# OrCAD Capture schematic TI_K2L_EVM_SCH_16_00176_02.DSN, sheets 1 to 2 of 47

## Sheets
1 PAGE19 : K2L_SOC-DDR3-1: size C; title: K2L DDR3; rev: 2.0; company: eInfochips; note: K2L EVM
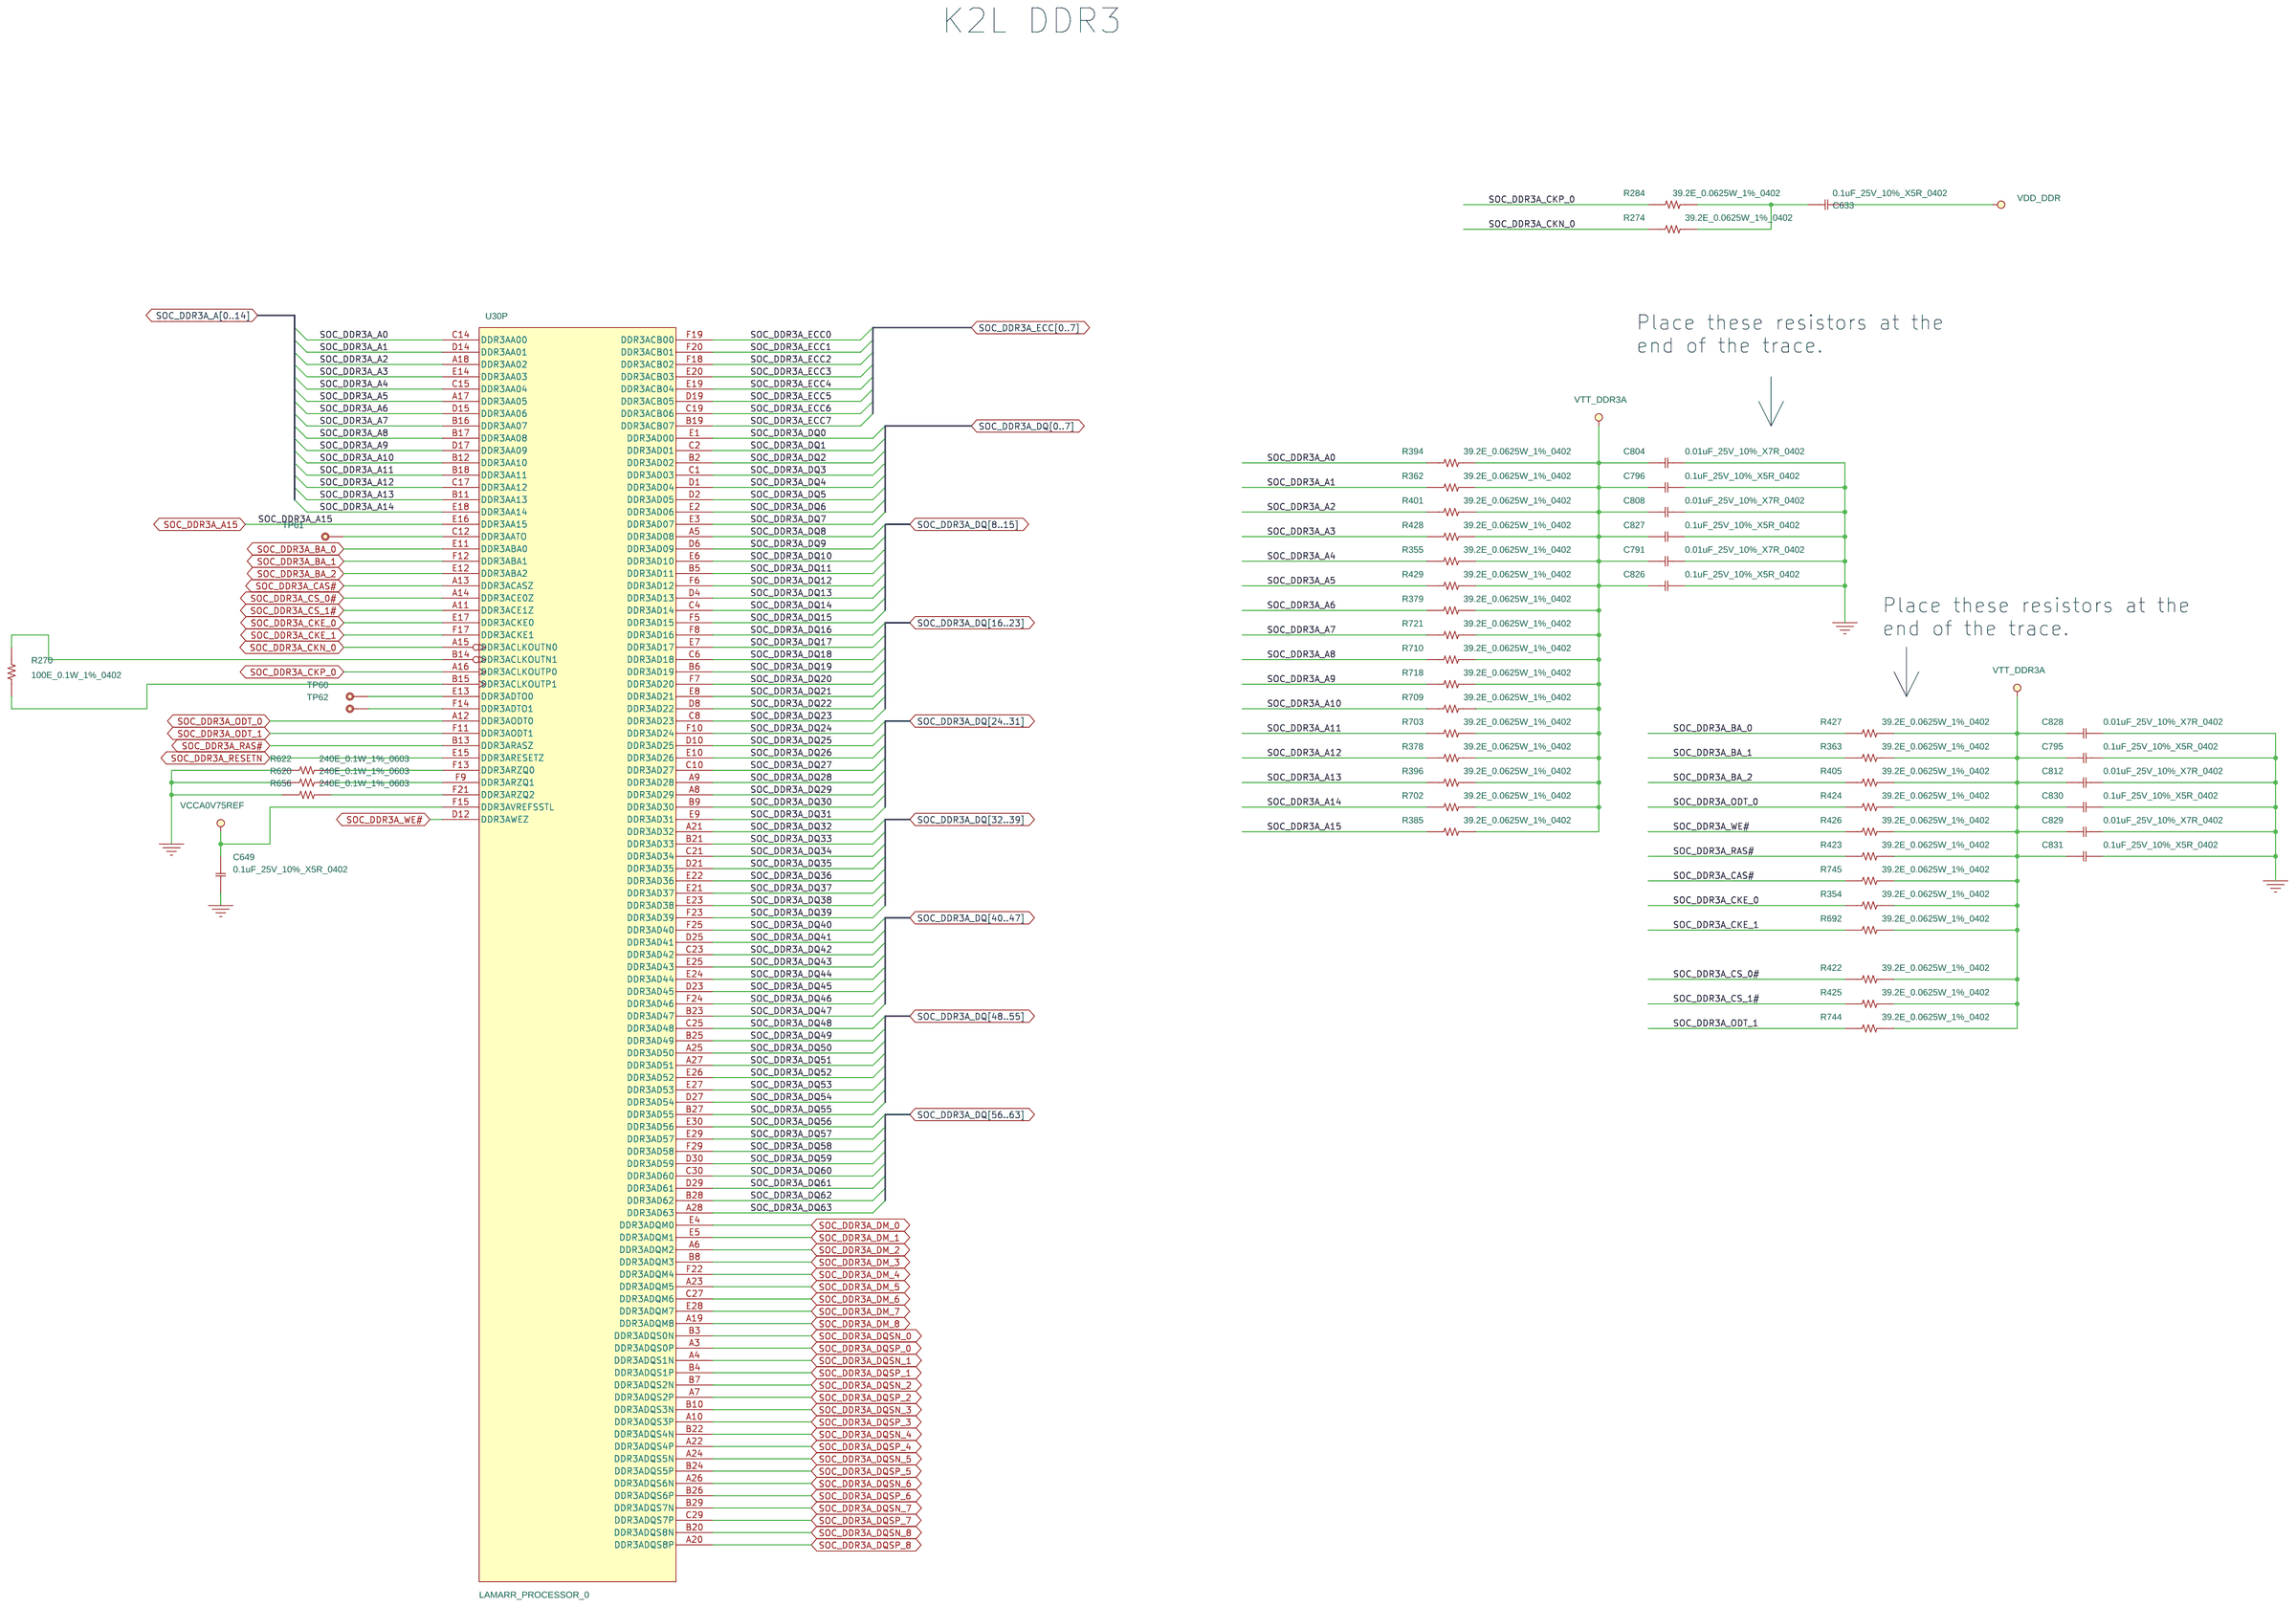
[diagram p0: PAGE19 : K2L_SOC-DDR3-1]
2 PAGE33 : K2L_ETH_PHY1: size C; title: Ethernet PHY, Magnetics for 2 channel/ Tx/Rx,
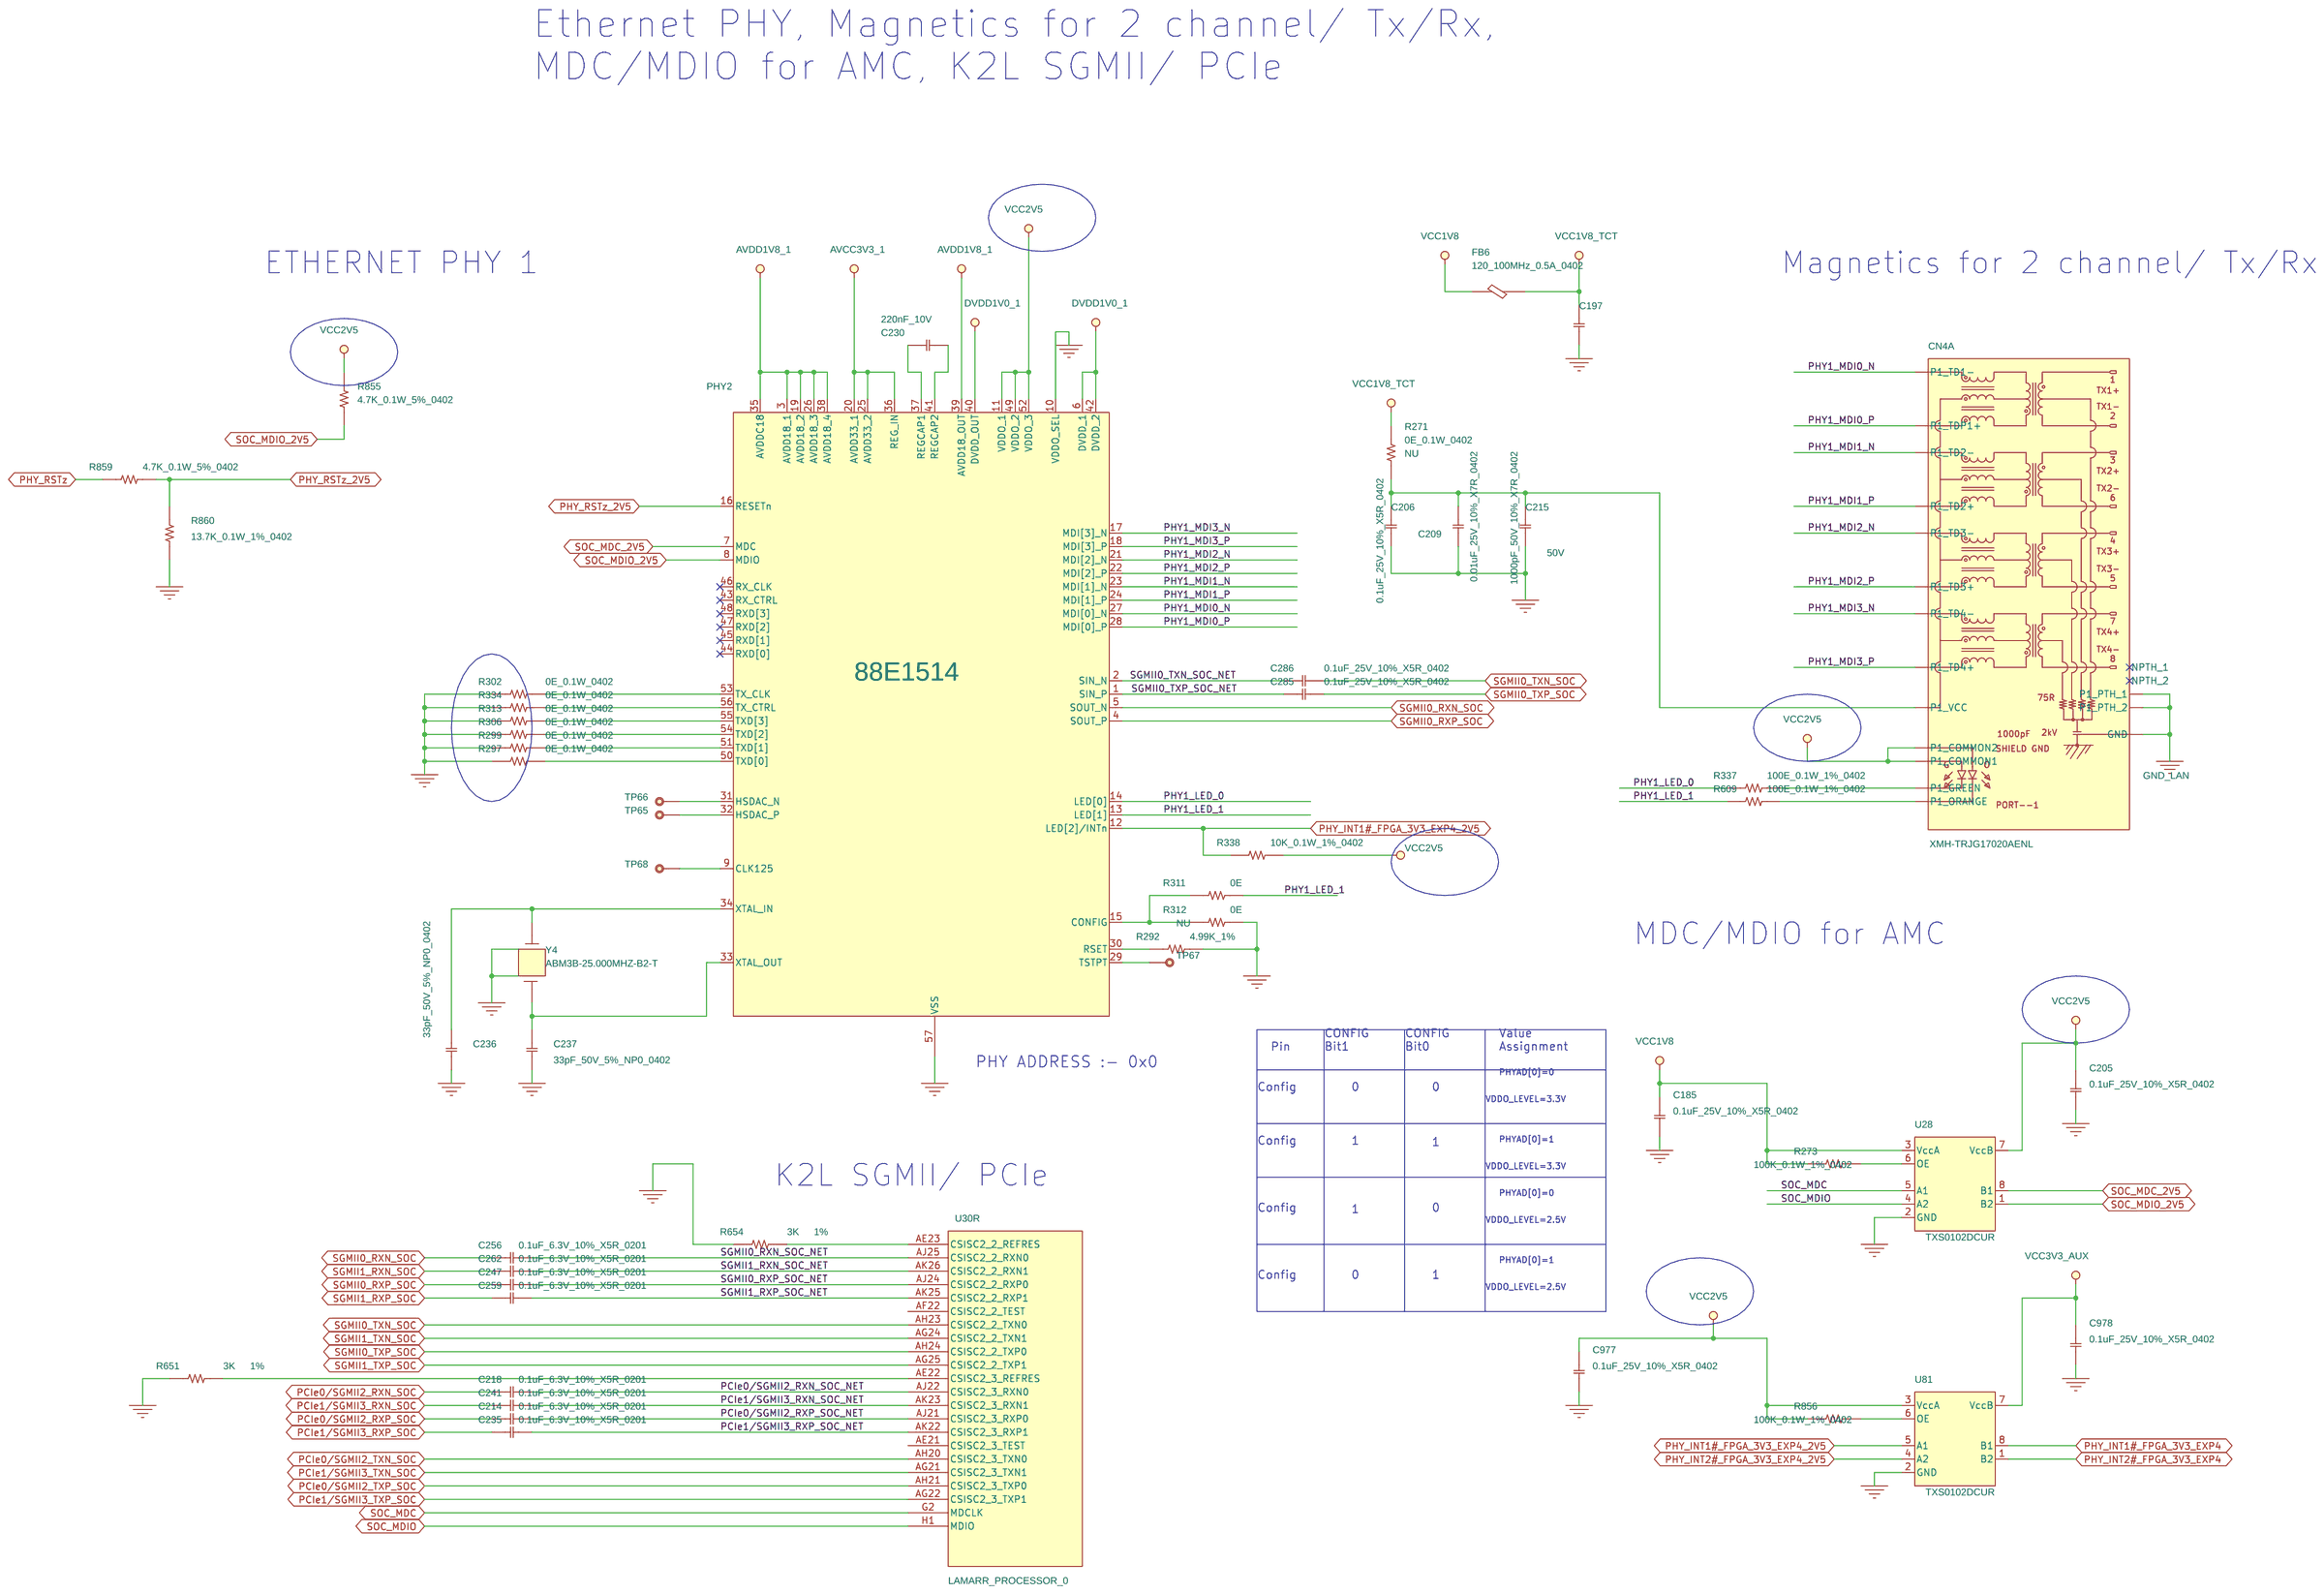
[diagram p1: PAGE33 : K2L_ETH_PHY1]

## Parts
sheet PAGE19 : K2L_SOC-DDR3-1
C633  0.1uF_25V_10%_X5R_0402  [C0402]
C649  0.1uF_25V_10%_X5R_0402  [C0402]
C791  0.01uF_25V_10%_X7R_0402  [C0402]
C795  0.1uF_25V_10%_X5R_0402  [C0402]
C796  0.1uF_25V_10%_X5R_0402  [C0402]
C804  0.01uF_25V_10%_X7R_0402  [C0402]
C808  0.01uF_25V_10%_X7R_0402  [C0402]
C812  0.01uF_25V_10%_X7R_0402  [C0402]
C826  0.1uF_25V_10%_X5R_0402  [C0402]
C827  0.1uF_25V_10%_X5R_0402  [C0402]
C828  0.01uF_25V_10%_X7R_0402  [C0402]
C829  0.01uF_25V_10%_X7R_0402  [C0402]
C830  0.1uF_25V_10%_X5R_0402  [C0402]
C831  0.1uF_25V_10%_X5R_0402  [C0402]
R270  100E_0.1W_1%_0402  [R0402]
R274  39.2E_0.0625W_1%_0402  [R0402]
R284  39.2E_0.0625W_1%_0402  [R0402]
R354  39.2E_0.0625W_1%_0402  [R0402]
R355  39.2E_0.0625W_1%_0402  [R0402]
R362  39.2E_0.0625W_1%_0402  [R0402]
R363  39.2E_0.0625W_1%_0402  [R0402]
R378  39.2E_0.0625W_1%_0402  [R0402]
R379  39.2E_0.0625W_1%_0402  [R0402]
R385  39.2E_0.0625W_1%_0402  [R0402]
R394  39.2E_0.0625W_1%_0402  [R0402]
R396  39.2E_0.0625W_1%_0402  [R0402]
R401  39.2E_0.0625W_1%_0402  [R0402]
R405  39.2E_0.0625W_1%_0402  [R0402]
R422  39.2E_0.0625W_1%_0402  [R0402]
R423  39.2E_0.0625W_1%_0402  [R0402]
R424  39.2E_0.0625W_1%_0402  [R0402]
R425  39.2E_0.0625W_1%_0402  [R0402]
R426  39.2E_0.0625W_1%_0402  [R0402]
R427  39.2E_0.0625W_1%_0402  [R0402]
R428  39.2E_0.0625W_1%_0402  [R0402]
R429  39.2E_0.0625W_1%_0402  [R0402]
R620  240E_0.1W_1%_0603  [R0603]
R622  240E_0.1W_1%_0603  [R0603]
R656  240E_0.1W_1%_0603  [R0603]
R692  39.2E_0.0625W_1%_0402  [R0402]
R702  39.2E_0.0625W_1%_0402  [R0402]
R703  39.2E_0.0625W_1%_0402  [R0402]
R709  39.2E_0.0625W_1%_0402  [R0402]
R710  39.2E_0.0625W_1%_0402  [R0402]
R718  39.2E_0.0625W_1%_0402  [R0402]
R721  39.2E_0.0625W_1%_0402  [R0402]
R744  39.2E_0.0625W_1%_0402  [R0402]
R745  39.2E_0.0625W_1%_0402  [R0402]
TP60  TP  [TP-S40]
TP61  TP  [TP-S40]
TP62  TP  [TP-S40]
sheet PAGE24 : K2L_JTAG
U30  LAMARR_PROCESSOR_0  [SKTBGA_Z3566_SS900-RHFB-BGA080]  (sections A,B,C,D,E,F,G,H,I,J,K,L,M,N,O,P,Q,R,S,T,U)
sheet PAGE33 : K2L_ETH_PHY1
C185  0.1uF_25V_10%_X5R_0402  [C0402]
C197  0.1uF_25V_10%_X5R_0402  [C0402]
C205  0.1uF_25V_10%_X5R_0402  [C0402]
C206  0.1uF_25V_10%_X5R_0402  [C0402]
C209  0.01uF_25V_10%_X7R_0402  [C0402]
C214  0.1uF_6.3V_10%_X5R_0201  [CC0201]
C215  1000pF_50V_10%_X7R_0402  [C0402]
C218  0.1uF_6.3V_10%_X5R_0201  [CC0201]
C230  220nF_10V  [C0402]
C235  0.1uF_6.3V_10%_X5R_0201  [CC0201]
C236  33pF_50V_5%_NP0_0402  [C0402]
C237  33pF_50V_5%_NP0_0402  [C0402]
C241  0.1uF_6.3V_10%_X5R_0201  [CC0201]
C247  0.1uF_6.3V_10%_X5R_0201  [CC0201]
C256  0.1uF_6.3V_10%_X5R_0201  [CC0201]
C259  0.1uF_6.3V_10%_X5R_0201  [CC0201]
C262  0.1uF_6.3V_10%_X5R_0201  [CC0201]
C285  0.1uF_25V_10%_X5R_0402  [C0402]
C286  0.1uF_25V_10%_X5R_0402  [C0402]
C977  0.1uF_25V_10%_X5R_0402  [C0402]
C978  0.1uF_25V_10%_X5R_0402  [C0402]
CN4  XMH-TRJG17020AENL  [XMULTIPLE_XMH-TRJG17020AENL]  (sections A,B)
FB6  120_100MHz_0.5A_0402  [L0402]
PHY2  88E1514  [QFN50P800X800X100-57N]
R271  0E_0.1W_0402  [R0402]
R273  100K_0.1W_1%_0402  [R0402]
R292  4.99K_1%  [R0402]
R297  0E_0.1W_0402  [R0402]
R299  0E_0.1W_0402  [R0402]
R302  0E_0.1W_0402  [R0402]
R306  0E_0.1W_0402  [R0402]
R311  0E  [R0402]
R312  0E  [R0402]
R313  0E_0.1W_0402  [R0402]
R334  0E_0.1W_0402  [R0402]
R337  100E_0.1W_1%_0402  [R0402]
R338  10K_0.1W_1%_0402  [R0402]
R609  100E_0.1W_1%_0402  [R0402]
R651  3K  [RC0201_IPC7351_EINF]
R654  3K  [RC0201_IPC7351_EINF]
R855  4.7K_0.1W_5%_0402  [R0402]
R856  100K_0.1W_1%_0402  [R0402]
R859  4.7K_0.1W_5%_0402  [R0402]
R860  13.7K_0.1W_1%_0402  [R0402]
TP65  TP  [TP-S40]
TP66  TP  [TP-S40]
TP67  TP  [TP-S40]
TP68  TP  [TP-S40]
U28  TXS0102DCUR  [VSSOP50P310_8]
U81  TXS0102DCUR  [VSSOP50P310_8]
Y4  ABM3B-25.000MHZ-B2-T  [XTAL_ABM3B]

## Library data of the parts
C633 = 11_C_0: CAP CER 0.1UF 25V 10% X5R 0402; Avalue_Part_Number: E1123510400H; Distributor_name: DIGIKEY; Distributor_part_number: 445-4964-1-ND; EIC Part#: 03_00470_02; GROUP: CPU1; Manufacture: TDK Corporation; Manufacture Part Number: C1005X5R1E104K050BC; Manufacture(English): TDK Corporation; Manufacture_Part_Number: GRM155R71C104KA88D; Manufacturer: TDK Corporation; Manufacturer_Part_No: C1005X5R1E104K050BC; Mfg: Murata Electronics North America; Mfg Part#: 03_00470_02; Mfr_name: TDK Corporation; Mfr_part_number: C1005X5R1E104K050BC; Package: 0402; Price @ 1: 0.10000; Price @ 1K: 0.00420; ProcessType: SMT; ROOM: CPU1; Tolerance: 10%; Vendor: DIGIKEY; Vendor Part#: 445-4964-1-ND; Vendor_Part_No: 445-4964-1-ND; eI Part#: 03_00470_02
C649 C795 C796 C826 C827 C830 C831 = 11_C_0: CAP CER 0.1UF 25V 10% X5R 0402; Avalue_Part_Number: E1123510400H; Distributor_name: DIGIKEY; Distributor_part_number: 445-4964-1-ND; EIC Part#: 03_00470_02; MOUNTED: <MOUNTED>; Manufacture: TDK Corporation; Manufacture Part Number: C1005X5R1E104K050BC; Manufacture(English): TDK Corporation; Manufacture_Part_Number: GRM155R71C104KA88D; Manufacturer: TDK Corporation; Manufacturer_Part_No: C1005X5R1E104K050BC; Mfg: Murata Electronics North America; Mfg Part#: 03_00470_02; Mfr_name: TDK Corporation; Mfr_part_number: C1005X5R1E104K050BC; Package: 0402; Price @ 1: 0.10000; Price @ 1K: 0.00420; ProcessType: SMT; Tolerance: 10%; Vendor: DIGIKEY; Vendor Part#: 445-4964-1-ND; Vendor_Part_No: 445-4964-1-ND; eI Part#: 03_00470_02
C791 C804 C808 C812 C828 C829 = 11_C_0: CAP CER 10000PF 25V 10% X7R 0402; Advansus_Part_Number: 11G232110312030; Distributor_name: DIGIKEY; Distributor_part_number: 445-1260-1-ND; EIC Part#: 03_00029_04; GROUP: CPU1; Manufacture: TDK Corporation; Manufacture Part Number: C1005X7R1E103K; Manufacture(English): TDK Corporation; Manufacture_Part_Number: C1005X7R1E103K; Manufacturer: TDK Corporation; Manufacturer_Part_No: C1005X7R1E103K; Mfg: TDK Corporation; Mfg Part#: 03_00029_04; Mfr_name: TDK Corporation; Mfr_part_number: C1005X7R1E103K; Package: 0402; Part_Number: 1121610790; Price @ 1: 0.10000; Price @ 10K: 0.00420; Price @ 1K: 0.00600; ProcessType: SMT; ROOM: CPU1; Tolerance: 10%; Vendor: DIGIKEY; Vendor_Part_No: 445-1260-1-ND; eI Part#: 03_00029_04
R270 = 10_R_0: RES 100 OHM 1/10W 1% 0402 SMD; Characteristic: 1%; Distributor_name: DIGIKEY; Distributor_part_number: P100LCT-ND; EIC Part#: 02_00043_02; Manufacture: Panasonic - ECG; Manufacture Part Number: ERJ-2RKF1000X; Manufacture(English): Panasonic - ECG; Manufacture_Part_Number: ERJ-2RKF1000X; Manufacturer: Panasonic - ECG; Manufacturer_Part_No: ERJ-2RKF1000X; Mfg: Panasonic Electronic Components; Mfg Part#: 02_00043_02; Mfr_name: Panasonic - ECG; Mfr_part_number: ERJ-2RKF1000X; Package: 0402; Part_Number: 105A510004; Price @ 1: 0.10000; Price @ 10K: 0.00347; Price @ 1K: 0.00672; ProcessType: SMT; Tolerance: 1%; Vendor: DIGIKEY; Vendor_Part_No: P100LCT-ND; eI Part#: 02_00019_01
R274 R284 R354 R423 R426 R427 = 10_R_0: RES 39.2 OHM 1/16W 1% 0402 SMD; Distributor_name: DIGIKEY; Distributor_part_number: P39.2LCT-ND; EIC Part#: 02_00195_04; Manufacture: Panasonic - ECG; Manufacture Part Number: ERJ-2RKF39R2X; Manufacture(English): Panasonic - ECG; Manufacture_Part_Number: ERJ-2RKF39R2X; Manufacturer: Panasonic - ECG; Manufacturer_Part_No: ERJ-2RKF39R2X; Mfg: Panasonic Electronic Components; Mfg Part#: 02_00195_04; Mfr_name: Panasonic - ECG; Mfr_part_number: ERJ-2RKF39R2X; Package: 0402; Part_Number: 105A53926A; Price @ 1: 0.10000; Price @ 10K: 0.00347; Price @ 1K: 0.00672; ProcessType: SMT; Tolerance: 1%; Vendor: DIGIKEY; Vendor_Part_No: P39.2LCT-ND; eI Part#: 02_00195_04
R355 R401 R424 R692 = 10_R_0: RES 39.2 OHM 1/16W 1% 0402 SMD; Distributor_name: DIGIKEY; Distributor_part_number: P39.2LCT-ND; EIC Part#: 02_00195_04; Manufacture: Panasonic - ECG; Manufacture Part Number: ERJ-2RKF39R2X; Manufacture(English): Panasonic - ECG; Manufacture_Part_Number: ERJ-2RKF39R2X; Manufacturer: Panasonic - ECG; Manufacturer_Part_No: ERJ-2RKF39R2X; Mfg: Panasonic Electronic Components; Mfg Part#: 02_00195_04; Mfr_name: Panasonic - ECG; Mfr_part_number: ERJ-2RKF39R2X; Package: 0402; Part_Number: 105A53926A; Price @ 1: 0.10000; Price @ 10K: 0.00347; Price @ 1K: 0.00672; ProcessType: SMT; Tolerance: 1%; Vendor: DIGIKEY; Vendor_Part_No: P39.2LCT-ND; eI Part#: 02_00734_01
R362 R385 R396 R744 = 10_R_0: RES 39.2 OHM 1/16W 1% 0402 SMD; Distributor_name: DIGIKEY; Distributor_part_number: P39.2LCT-ND; EIC Part#: 02_00195_04; Manufacture: Panasonic - ECG; Manufacture Part Number: ERJ-2RKF39R2X; Manufacture(English): Panasonic - ECG; Manufacture_Part_Number: ERJ-2RKF39R2X; Manufacturer: Panasonic - ECG; Manufacturer_Part_No: ERJ-2RKF39R2X; Mfg: Panasonic Electronic Components; Mfg Part#: 02_00195_04; Mfr_name: Panasonic - ECG; Mfr_part_number: ERJ-2RKF39R2X; Package: 0402; Part_Number: 105A53926A; Price @ 1: 0.10000; Price @ 10K: 0.00347; Price @ 1K: 0.00672; ProcessType: SMT; Tolerance: 1%; Vendor: DIGIKEY; Vendor_Part_No: P39.2LCT-ND; eI Part#: 02_00027_01
R363 = 10_R_0: RES 39.2 OHM 1/16W 1% 0402 SMD; Distributor_name: DIGIKEY; Distributor_part_number: P39.2LCT-ND; EIC Part#: 02_00195_04; Manufacture: Panasonic - ECG; Manufacture Part Number: ERJ-2RKF39R2X; Manufacture(English): Panasonic - ECG; Manufacture_Part_Number: ERJ-2RKF39R2X; Manufacturer: Panasonic - ECG; Manufacturer_Part_No: ERJ-2RKF39R2X; Mfg: Panasonic Electronic Components; Mfg Part#: 02_00195_04; Mfr_name: Panasonic - ECG; Mfr_part_number: ERJ-2RKF39R2X; Package: 0402; Part_Number: 105A53926A; Price @ 1: 0.10000; Price @ 10K: 0.00347; Price @ 1K: 0.00672; ProcessType: SMT; Tolerance: 1%; Vendor: DIGIKEY; Vendor_Part_No: P39.2LCT-ND; eI Part#: TBD
R378 R703 = 10_R_0: RES 39.2 OHM 1/16W 1% 0402 SMD; Distributor_name: DIGIKEY; Distributor_part_number: P39.2LCT-ND; EIC Part#: 02_00195_04; Manufacture: Panasonic - ECG; Manufacture Part Number: ERJ-2RKF39R2X; Manufacture(English): Panasonic - ECG; Manufacture_Part_Number: ERJ-2RKF39R2X; Manufacturer: Panasonic - ECG; Manufacturer_Part_No: ERJ-2RKF39R2X; Mfg: Panasonic Electronic Components; Mfg Part#: 02_00195_04; Mfr_name: Panasonic - ECG; Mfr_part_number: ERJ-2RKF39R2X; Package: 0402; Part_Number: 105A53926A; Price @ 1: 0.10000; Price @ 10K: 0.00347; Price @ 1K: 0.00672; ProcessType: SMT; Tolerance: 1%; Vendor: DIGIKEY; Vendor_Part_No: P39.2LCT-ND; eI Part#: 02_00348_01
R379 R425 R428 R429 R710 = 10_R_0: RES 39.2 OHM 1/16W 1% 0402 SMD; Distributor_name: DIGIKEY; Distributor_part_number: P39.2LCT-ND; EIC Part#: 02_00195_04; Manufacture: Panasonic - ECG; Manufacture Part Number: ERJ-2RKF39R2X; Manufacture(English): Panasonic - ECG; Manufacture_Part_Number: ERJ-2RKF39R2X; Manufacturer: Panasonic - ECG; Manufacturer_Part_No: ERJ-2RKF39R2X; Mfg: Panasonic Electronic Components; Mfg Part#: 02_00195_04; Mfr_name: Panasonic - ECG; Mfr_part_number: ERJ-2RKF39R2X; Package: 0402; Part_Number: 105A53926A; Price @ 1: 0.10000; Price @ 10K: 0.00347; Price @ 1K: 0.00672; ProcessType: SMT; Tolerance: 1%; Vendor: DIGIKEY; Vendor_Part_No: P39.2LCT-ND; eI Part#: 02_00019_01
R394 R702 R745 = 10_R_0: RES 39.2 OHM 1/16W 1% 0402 SMD; Distributor_name: DIGIKEY; Distributor_part_number: P39.2LCT-ND; EIC Part#: 02_00195_04; Manufacture: Panasonic - ECG; Manufacture Part Number: ERJ-2RKF39R2X; Manufacture(English): Panasonic - ECG; Manufacture_Part_Number: ERJ-2RKF39R2X; Manufacturer: Panasonic - ECG; Manufacturer_Part_No: ERJ-2RKF39R2X; Mfg: Panasonic Electronic Components; Mfg Part#: 02_00195_04; Mfr_name: Panasonic - ECG; Mfr_part_number: ERJ-2RKF39R2X; Package: 0402; Part_Number: 105A53926A; Price @ 1: 0.10000; Price @ 10K: 0.00347; Price @ 1K: 0.00672; ProcessType: SMT; Tolerance: 1%; Vendor: DIGIKEY; Vendor_Part_No: P39.2LCT-ND; eI Part#: 02_00334_02
R405 R709 = 10_R_0: RES 39.2 OHM 1/16W 1% 0402 SMD; Distributor_name: DIGIKEY; Distributor_part_number: P39.2LCT-ND; EIC Part#: 02_00195_04; Manufacture: Panasonic - ECG; Manufacture Part Number: ERJ-2RKF39R2X; Manufacture(English): Panasonic - ECG; Manufacture_Part_Number: ERJ-2RKF39R2X; Manufacturer: Panasonic - ECG; Manufacturer_Part_No: ERJ-2RKF39R2X; Mfg: Panasonic Electronic Components; Mfg Part#: 02_00195_04; Mfr_name: Panasonic - ECG; Mfr_part_number: ERJ-2RKF39R2X; Package: 0402; Part_Number: 105A53926A; Price @ 1: 0.10000; Price @ 10K: 0.00347; Price @ 1K: 0.00672; ProcessType: SMT; Tolerance: 1%; Vendor: DIGIKEY; Vendor_Part_No: P39.2LCT-ND; eI Part#: 02_00043_02
R422 = 10_R_0: RES 39.2 OHM 1/16W 1% 0402 SMD; Distributor_name: DIGIKEY; Distributor_part_number: P39.2LCT-ND; EIC Part#: 02_00195_04; Manufacture: Panasonic - ECG; Manufacture Part Number: ERJ-2RKF39R2X; Manufacture(English): Panasonic - ECG; Manufacture_Part_Number: ERJ-2RKF39R2X; Manufacturer: Panasonic - ECG; Manufacturer_Part_No: ERJ-2RKF39R2X; Mfg: Panasonic Electronic Components; Mfg Part#: 02_00195_04; Mfr_name: Panasonic - ECG; Mfr_part_number: ERJ-2RKF39R2X; Package: 0402; Part_Number: 105A53926A; Price @ 1: 0.10000; Price @ 10K: 0.00347; Price @ 1K: 0.00672; ProcessType: SMT; Tolerance: 1%; Vendor: DIGIKEY; Vendor_Part_No: P39.2LCT-ND; eI Part#: 02_00266_01
R620 R622 R656 = 10_R_0: RES 240 OHM 1/10W 1% 0603 SMD; Distributor_name: DIGIKEY; Distributor_part_number: P240HCT-ND; EIC Part#: 02_00734_01; Manufacture: Panasonic - ECG; Manufacture Part Number: ERJ-3EKF2400V; Manufacture(English): Panasonic - ECG; Manufacture_Part_Number: ERJ-3EKF2400V; Manufacturer: Panasonic - ECG; Manufacturer_Part_No: ERJ-3EKF2400V; Mfg Part#: 02_00734_01; Mfr_name: Panasonic - ECG; Mfr_part_number: ERJ-3EKF2400V; Package: 0603; ProcessType: SMT; RoHS: Yes; Vendor: DIGIKEY; Vendor Part#: P240HCT-ND; Vendor_Part_No: P240HCT-ND; eI Part#: 02_00266_01
R718 = 10_R_0: RES 39.2 OHM 1/16W 1% 0402 SMD; Distributor_name: DIGIKEY; Distributor_part_number: P39.2LCT-ND; EIC Part#: 02_00195_04; Manufacture: Panasonic - ECG; Manufacture Part Number: ERJ-2RKF39R2X; Manufacture(English): Panasonic - ECG; Manufacture_Part_Number: ERJ-2RKF39R2X; Manufacturer: Panasonic - ECG; Manufacturer_Part_No: ERJ-2RKF39R2X; Mfg: Panasonic Electronic Components; Mfg Part#: 02_00195_04; Mfr_name: Panasonic - ECG; Mfr_part_number: ERJ-2RKF39R2X; Package: 0402; Part_Number: 105A53926A; Price @ 1: 0.10000; Price @ 10K: 0.00347; Price @ 1K: 0.00672; ProcessType: SMT; Tolerance: 1%; Vendor: DIGIKEY; Vendor_Part_No: P39.2LCT-ND; eI Part#: 02_00032_01
R721 = 10_R_0: RES 39.2 OHM 1/16W 1% 0402 SMD; Distributor_name: DIGIKEY; Distributor_part_number: P39.2LCT-ND; EIC Part#: 02_00195_04; Manufacture: Panasonic - ECG; Manufacture Part Number: ERJ-2RKF39R2X; Manufacture(English): Panasonic - ECG; Manufacture_Part_Number: ERJ-2RKF39R2X; Manufacturer: Panasonic - ECG; Manufacturer_Part_No: ERJ-2RKF39R2X; Mfg: Panasonic Electronic Components; Mfg Part#: 02_00195_04; Mfr_name: Panasonic - ECG; Mfr_part_number: ERJ-2RKF39R2X; Package: 0402; Part_Number: 105A53926A; Price @ 1: 0.10000; Price @ 10K: 0.00347; Price @ 1K: 0.00672; ProcessType: SMT; Tolerance: 1%; Vendor: DIGIKEY; Vendor_Part_No: P39.2LCT-ND; eI Part#: 02_00234_02
TP60-TP62 TP65-TP68 = 00_TP-S40_0: TEST PAD TP; Distributor_name: NA; Distributor_part_number: NA; EIC Part#: NA; Manufacture: NA; Manufacture Part Number: NA; Manufacture(English): NA; Manufacture_Part_Number: NA; Manufacturer: NA; Manufacturer_Part_No: NA; Mfg: NA; Mfg Part#: NA; Mfr_name: NA; Mfr_part_number: NA; Oper. Temp. Range: --NA--; Package: --NA--; Price @ 1: NA; Price @ 10K: NA; Price @ 1K: NA; ProcessType: SMT; RoHS: Yes; Vendor: NA; Vendor Part#: --NA--; Vendor_Part_No: NA; eI Part#: NA
U30 = LAMARR_PROCESSOR_7: LAMARR-SoC 900BGA 4DSP + 2ARM; Color: Default; Distributor_name: TBD; Distributor_part_number: TBD; EIC Part#: TBD; Location X-Coordinate: 0; Location Y-Coordinate: 0; Manufacture: TI; Manufacture Part Number: TCI6630K2L; Manufacture(English): TI; Manufacture_Part_Number: TCI6630K2L; Manufacturer: TI; Manufacturer_Part_No: TCI6630K2L; Mfg: TI; Mfg Part#: TBD; Mfr_name: TI; Mfr_part_number: LAMARR-SoC; Price @ 1: TBD; Price @ 10K: TBD; Price @ 1K: TBD; Primitive: DEFAULT; SPLIT_INST: TRUE; SWAP_INFO: (S1+S2+S3+S4+S5+S6+S7+S8+S9+S10+S11+S12+S13+S14+S15+S16+S17+S18+S19+S20+S21); Vendor: TBD; Vendor_Part_No: TBD; eI Part#: TBD
C185 C205 C977 C978 = 11_C_12: CAP CER 0.1UF 25V 10% X5R 0402; Alt Mfg: Taiyo Yuden; Distributor_name: DIGIKEY; Distributor_part_number: 445-4964-1-ND; EIC Part#: 03_00470_02; MOUNTED: <MOUNTED>; Manufacture: TDK Corporation; Manufacture Part Number: C1005X5R1E104K050BC; Manufacture(English): TDK Corporation; Manufacture_Part_Number: GRM155R61E104KA87D; Manufacturer: TDK Corporation; Manufacturer_Part_No: C1005X5R1E104K050BC; Mfg: Murata Electronics North America; Mfg Part#: 03_00470_02; Mfr_name: TDK Corporation; Mfr_part_number: C1005X5R1E104K050BC; Oper. Temp. Range: -55°C ~ 85°C; Package: 0402; Price @ 1: 0.10000; Price @ 1K: 0.00960; ProcessType: SMT; RoHS: Yes; Tolerance: 10%; Vendor: DIGIKEY; Vendor Part#: 445-4964-1-ND; Vendor_Part_No: 445-4964-1-ND; eI Part#: 03_00470_02
C197 C206 C285 C286 = 11_C_12: CAP CER 0.1UF 25V 10% X5R 0402; Alt Mfg: Taiyo Yuden; Distributor_name: DIGIKEY; Distributor_part_number: 445-4964-1-ND; EIC Part#: 03_00470_02; MOUNTED: <MOUNTED>; Manufacture: TDK Corporation; Manufacture Part Number: C1005X5R1E104K050BC; Manufacture(English): TDK Corporation; Manufacture_Part_Number: GRM155R61E104KA87D; Manufacturer: TDK Corporation; Manufacturer_Part_No: C1005X5R1E104K050BC; Mfg: Murata Electronics North America; Mfg Part#: 03_00470_02; Mfr_name: TDK Corporation; Mfr_part_number: C1005X5R1E104K050BC; Oper. Temp. Range: -55°C ~ 85°C; Package: 0402; Price @ 1: 0.10000; Price @ 1K: 0.00960; ProcessType: SMT; RoHS: Yes; Vendor: DIGIKEY; Vendor Part#: 445-4964-1-ND; Vendor_Part_No: 445-4964-1-ND; eI Part#: 03_00470_02
C209 = 11_C_0: CAP CER 10000PF 25V 10% X7R 0402; Alt Mfg: Murata; Alt Mfg Part#: GRM155R71C103KA01D; Distributor_name: DIGIKEY; Distributor_part_number: 445-1260-1-ND; EIC Part#: 03_00029_04; Manufacture: TDK Corporation; Manufacture Part Number: C1005X7R1E103K; Manufacture(English): TDK Corporation; Manufacture_Part_Number: C1005X7R1E103K; Manufacturer: TDK Corporation; Manufacturer_Part_No: C1005X7R1E103K; Mfg: TDK Corporation; Mfg Part#: 03_00029_04; Mfr_name: TDK Corporation; Mfr_part_number: C1005X7R1E103K; Oper. Temp. Range: -55C to 125C; Package: 0402; Price @ 1: 0.10000; Price @ 10K: 0.00420; Price @ 1K: 0.00600; ProcessType: SMT; RoHS: Yes; Tolerance: 10%; Vendor: DIGIKEY; Vendor Part#: PCC103BQCT-ND; Vendor_Part_No: 445-1260-1-ND; Voltage: 16V; eI Part#: 03_00029_04
C214 C218 C235 C241 C247 C256 C259 C262 = 11_C_12: CAP CER 0.1UF 6.3V 10% X5R 0201; Alt Mfg: Taiyo Yuden; Alt Mfg Part#: TMK105BJ104KV-F; Characteristic: <Characteristic>; Distributor_name: DIGIKEY; Distributor_part_number: 445-1796-1-ND; EIC Part#: 03_00583_01; Manufacture: TDK Corporation; Manufacture Part Number: C0603X5R0J104K030BC; Manufacture(English): TDK Corporation; Manufacture_Part_Number: C0603X5R0J104K030BC; Manufacturer: TDK Corporation; Manufacturer_Part_No: C0603X5R0J104K030BC; Mfg: TDK Corporation; Mfg Part#: 03_00583_01; Mfr_name: TDK Corporation; Mfr_part_number: C0603X5R0J104K030BC; Oper. Temp. Range: -55°C ~ 85°C; Package: 0201; Price @ 1: 0.10000; Price @ 10K: 0.00675; Price @ 1K: 0.00810; ProcessType: SMT; RoHS: Yes; Tolerance: 10%; Vendor: DIGIKEY; Vendor Part#: 445-1796-2-ND; Vendor_Part_No: 445-1796-1-ND; Voltage: 6.3V; eI Part#: 03_00583_01
C215 = 11_C_0: CAP CER 1000PF 50V 10% X7R 0402; Advansus_Part_Number: 11G232110214030; Distributor_name: DIGIKEY; Distributor_part_number: 1276-1493-1-ND; EIC Part#: 03_00591_01; Manufacture: Samsung; Manufacture Part Number: CL05B102KB5NFNC; Manufacture(English): Samsung; Manufacture_Part_Number: CL05B102KB5NFNC; Manufacturer: Samsung; Manufacturer_Part_No: CL05B102KB5NFNC; Mfg: Samsung; Mfg Part#: CL05B102KB5NFNC; Mfr_name: Samsung; Mfr_part_number: CL05B102KB5NFNC; Oper. Temp. Range: -55C to 85C; Package: 0402; Price @ 1: 0.10000; Price @ 10K: 0.00260; Price @ 1K: 0.00372; ProcessType: SMT; RoHS: Yes; Tolerance: 10%; Vendor: DIGIKEY; Vendor Part#: 1276-1493-1-ND; Vendor_Part_No: 1276-1493-1-ND; Voltage: 50V; eI Part#: 03_00591_01
C230 = Cap_Ceramic: CAP CER 0.22UF 10V 10% X5R 0402; Alt Mfg: Taiyo Yuden; Alt Mfg Part#: TMK105BJ104KV-F; Distributor_name: DIGIKEY; Distributor_part_number: 445-4985-1-ND; EIC Part#: TBD; MOUNTED: <MOUNTED>; Manufacture: TDK Corporation; Manufacture Part Number: C1005X5R1A224K050BC; Manufacture(English): TDK Corporation; Manufacturer: TDK Corporation; Manufacturer_Part_No: C1005X5R1A224K050BC; Mfg: TDK Corporation; Mfg Part#: TBD; Mfr_name: TDK Corporation; Mfr_part_number: C1005X5R1A224K050BC; Oper. Temp. Range: -55°C ~ 85°C; Package: 0402; ProcessType: SMT; RoHS: Yes; Tolerance: 10%; Vendor: DIGIKEY; Vendor Part#: 445-4985-1-ND; Vendor_Part_No: 445-4985-1-ND; Voltage: 10V; eI Part#: TBD
C236 C237 = 11_C_12: CAP CER 33PF 50V 5% NPO 0402; Characteristic: <Characteristic>; Distributor_name: DIGIKEY; Distributor_part_number: 311-1020-1-ND; EIC Part#: 03_00019_01; Manufacture: Yageo; Manufacture Part Number: CC0402JRNPO9BN330; Manufacture(English): Yageo; Manufacture_Part_Number: CC0402JRNPO9BN330; Manufacturer: Yageo; Manufacturer_Part_No: CC0402JRNPO9BN330; Mfg: Yageo; Mfg Part#: 03_00019_01; Mfr_name: Yageo; Mfr_part_number: CC0402JRNPO9BN330; Oper. Temp. Range: -55C to 85C; Package: 0402; Price @ 1: 0.10000; Price @ 10K: 0.00227; Price @ 1K: 0.00324; ProcessType: SMT; RoHS: Yes; Tolerance: 10%; Vendor: DIGIKEY; Vendor Part#: 311-1020-1-ND; Vendor_Part_No: 311-1020-1-ND; Voltage: 50V; eI Part#: 03_00019_01
CN4 = XMH-TRJG17020AENL_0: RJ45 connector with 1000 Base-T Integrated Magnetics; Alt Mfg: Bel Fuse Inc; Alt Mfg Part#: 0879-2C1R-54; Distributor_name: TBD; Distributor_part_number: TBD; EIC Part#: 09_00947_01; Manufacture: X Multiple; Manufacture(English): X Multiple; Manufacturer: X Multiple; Mfg Part#: 09_00947_01; Mfr_name: X Multiple; Vendor: TBD; Vendor_Part_No: TBD; eI Part#: 09_00947_01; CLASS: IO; Color: Default; Location X-Coordinate: 0; Location Y-Coordinate: 0; Primitive: DEFAULT
FB6 = 1212_BEAD_0: FERRITE CHIP 120 OHM 500MA 0402; Distributor_name: DIGIKEY; Distributor_part_number: 490-1005-1-ND; EIC Part#: 04_00075_01; Manufacture: Murata; Manufacture Part Number: BLM15AG121SN1D; Manufacture(English): Murata; Manufacture_Part_Number: BLM15AG121SN1D; Manufacturer: Murata; Manufacturer_Part_No: BLM15AG121SN1D; Mfg: Murata; Mfg Part#: BLM15AG121SN1D; Mfr_name: Murata; Mfr_part_number: BLM15AG121SN1D; Oper. Temp. Range: -55C to 85C; Package: 0402; ProcessType: SMT; RoHS: Yes; Tolerance: 25%; Vendor: DIGIKEY; Vendor Part#: 490-1005-1-ND; Vendor_Part_No: 490-1005-1-ND; eI Part#: 04_00075_01
PHY2 = 88E1512: Alt Mfg: MARVELL; Alt Mfg Part#: 88E1512-A0-NNP2C000; Distributor_name: Avnet Express; Distributor_part_number: 88E1514-XX-NNP2C000; EIC Part#: TBD; Manufacture: Marvell; Manufacture Part Number: 88E1514-XX-NNP2C000; Manufacture(English): Marvell; Manufacture_Part_Number: 88E1514-XX-NNP2C000; Manufacturer: Marvell; Manufacturer_Part_No: 88E1514-XX-NNP2C000; Mfg: Marvell; Mfg Part#: TBD; Mfr_name: Marvell; Mfr_part_number: 88E1514-XX-NNP2C000; Price @ 1: TBD; Price @ 10K: TBD; Price @ 1K: TBD; Vendor: Avnet Express; Vendor Part#: 88E1514-XX-NNP2C000; Vendor_Part_No: 88E1514-XX-NNP2C000; eI Part#: TBD
R271 = 10_R_0: RES 0.0 OHM 1/10W JUMP 0402 SMD; Characteristic: 5%; Distributor_name: DIGIKEY; Distributor_part_number: P0.0JCT-ND; EIC Part#: 02_00019_01; Manufacture: Panasonic - ECG; Manufacture Part Number: ERJ-2GE0R00X; Manufacture(English): Panasonic - ECG; Manufacture_Part_Number: ERJ-2GE0R00X; Manufacturer: Panasonic - ECG; Manufacturer_Part_No: ERJ-2GE0R00X; Mfg: Panasonic Electronic Components; Mfg Part#: 02_00019_01; Mfr_name: Panasonic - ECG; Mfr_part_number: ERJ-2GE0R00X; Mounting: NU; Mounting Status: NU; Mounting_Status: NU; Package: 0402; Part_Number: 105A700004; Price @ 1: 0.05000; Price @ 10K: 0.00248; Price @ 1K: 0.00480; ProcessType: SMT; Tolerance: 5%; Vendor: DIGIKEY; Vendor_Part_No: P0.0JCT-ND; eI Part#: 02_00019_01
R273 R856 = 10_R_0: RES 100K OHM 1/10W 1% 0402 SMD; Alt Mfg: Yageo; Alt Mfg Part#: RC0402FR-07100KL; Distributor_name: DIGIKEY; Distributor_part_number: P100KLCT-ND; EIC Part#: 02_00262_01; Manufacture: Panasonic - ECG; Manufacture Part Number: ERJ-2RKF1003X; Manufacture(English): Panasonic - ECG; Manufacture_Part_Number: ERJ-2RKF1003X; Manufacturer: Panasonic - ECG; Manufacturer_Part_No: ERJ-2RKF1003X; Mfg Part#: 02_00262_01; Mfr_name: Panasonic - ECG; Mfr_part_number: ERJ-2RKF1003X; Oper. Temp. Range: ±100ppm/°C; Package: 0402; ProcessType: SMT; RoHS: Yes; Tolerance: 1%; Vendor: DIGIKEY; Vendor Part#: P100KLCT-ND; Vendor_Part_No: P100KLCT-ND; eI Part#: 02_00027_01
R292 = 10_R_0: RES 4.99K OHM 1/10W 1% 0402 SMD; Alt Mfg: Yageo; Alt Mfg Part#: RC0402FR-071KL; Distributor_name: DIGIKEY; Distributor_part_number: P4.99KLCT-ND; EIC Part#: 02_00038_01; MOUNTED: <MOUNTED>; Manufacture: Panasonic - ECG; Manufacture Part Number: ERJ-2RKF4991X; Manufacture(English): Panasonic - ECG; Manufacture_Part_Number: ERJ-2RKF4991X; Manufacturer: Panasonic - ECG; Manufacturer_Part_No: ERJ-2RKF4991X; Mfg Part#: 02_00038_01; Mfr_name: Panasonic - ECG; Mfr_part_number: ERJ-2RKF4991X; Oper. Temp. Range: -55C to 125C; Package: 0402; ProcessType: SMT; RoHS: Yes; Tolerance: 1%; Vendor: DIGIKEY; Vendor Part#: P4.99KLCT-ND; Vendor_Part_No: P4.99KLCT-ND; eI Part#: 02_00882_01
R297 R299 R302 R306 R311 R313 R334 = 10_R_0: RES 0.0 OHM 1/10W JUMP 0402 SMD; Alt Mfg: Yageo; Distributor_name: DIGIKEY; Distributor_part_number: P0.0JCT-ND; EIC Part#: 02_00019_01; Manufacture: Panasonic - ECG; Manufacture Part Number: ERJ-2GE0R00X; Manufacture(English): Panasonic - ECG; Manufacture_Part_Number: ERJ-2GE0R00X; Manufacturer: Panasonic - ECG; Manufacturer_Part_No: ERJ-2GE0R00X; Mfg Part#: 02_00019_01; Mfr_name: Panasonic - ECG; Mfr_part_number: ERJ-2GE0R00X; Oper. Temp. Range: -55C to 125C; Package: 0402; ProcessType: SMT; Remark: Alt part is 1/16W; RoHS: Yes; Tolerance: 5%; Vendor: DIGIKEY; Vendor Part#: P0.0JCT-ND; Vendor_Part_No: P0.0JCT-ND; eI Part#: 02_00019_01
R312 = 10_R_0: RES 0.0 OHM 1/10W JUMP 0402 SMD; Alt Mfg: Yageo; Distributor_name: DIGIKEY; Distributor_part_number: P0.0JCT-ND; EIC Part#: 02_00019_01; Manufacture: Panasonic - ECG; Manufacture Part Number: ERJ-2GE0R00X; Manufacture(English): Panasonic - ECG; Manufacture_Part_Number: ERJ-2GE0R00X; Manufacturer: Panasonic - ECG; Manufacturer_Part_No: ERJ-2GE0R00X; Mfg Part#: 02_00019_01; Mfr_name: Panasonic - ECG; Mfr_part_number: ERJ-2GE0R00X; Mounting: NU; Mounting Status: NU; Mounting_Status: NU; Oper. Temp. Range: -55C to 125C; Package: 0402; ProcessType: SMT; Remark: Alt part is 1/16W; RoHS: Yes; Tolerance: 5%; Vendor: DIGIKEY; Vendor Part#: P0.0JCT-ND; Vendor_Part_No: P0.0JCT-ND; eI Part#: 02_00019_01
R337 = 10_R_0: RES 100 OHM 1/10W 1% 0402 SMD; Distributor_name: DIGIKEY; Distributor_part_number: P100LCT-ND; EIC Part#: 02_00043_02; Manufacture: Panasonic - ECG; Manufacture Part Number: ERJ-2RKF1000X; Manufacture(English): Panasonic - ECG; Manufacture_Part_Number: ERJ-2RKF1000X; Manufacturer: Panasonic - ECG; Manufacturer_Part_No: ERJ-2RKF1000X; Mfg Part#: 02_00043_02; Mfr_name: Panasonic - ECG; Mfr_part_number: ERJ-2RKF1000X; Oper. Temp. Range: -55C to 125C; Package: 0402; ProcessType: SMT; RoHS: Yes; Tolerance: 1%; Vendor: DIGIKEY; Vendor Part#: P100LCT-ND; Vendor_Part_No: P100LCT-ND; eI Part#: 02_00027_01
R338 = 10_R_0: RES 10K OHM 1/10W 1% 0402 SMD; Alt Mfg: Yageo; Alt Mfg Part#: RC0402FR-0710KL; Distributor_name: DIGIKEY; Distributor_part_number: P10.0KLCT-ND; EIC Part#: 02_00027_01; Manufacture: Panasonic - ECG; Manufacture Part Number: ERJ-2RKF1002X; Manufacture(English): Panasonic - ECG; Manufacture_Part_Number: ERJ-2RKF1002X; Manufacturer: Panasonic - ECG; Manufacturer_Part_No: ERJ-2RKF1002X; Mfg Part#: 02_00027_01; Mfr_name: Panasonic - ECG; Mfr_part_number: ERJ-2RKF1002X; Oper. Temp. Range: -55C ~ 125C; Package: 0402; Price @ 1: 0.10000; Price @ 10K: 0.00347; Price @ 1K: 0.00672; ProcessType: SMT; Remark: Alt part is 1/16W; RoHS: Yes; Tolerance: 1%; Vendor: DIGIKEY; Vendor Part#: P10.0KLCT-ND; Vendor_Part_No: P10.0KLCT-ND; eI Part#: 02_00027_01
R609 = 10_R_0: RES 100 OHM 1/10W 1% 0402 SMD; Distributor_name: DIGIKEY; Distributor_part_number: P100LCT-ND; EIC Part#: 02_00043_02; Manufacture: Panasonic - ECG; Manufacture Part Number: ERJ-2RKF1000X; Manufacture(English): Panasonic - ECG; Manufacture_Part_Number: ERJ-2RKF1000X; Manufacturer: Panasonic - ECG; Manufacturer_Part_No: ERJ-2RKF1000X; Mfg Part#: 02_00043_02; Mfr_name: Panasonic - ECG; Mfr_part_number: ERJ-2RKF1000X; Oper. Temp. Range: -55C to 125C; Package: 0402; ProcessType: SMT; RoHS: Yes; Tolerance: 1%; Vendor: DIGIKEY; Vendor Part#: P100LCT-ND; Vendor_Part_No: P100LCT-ND; eI Part#: 02_00019_01
R651 R654 = 10_R_0: RES 3K OHM 1/20W 5% 0201 SMD; Characteristic: 1%; Distributor_name: DIGIKEY; EIC Part#: 02_00960_01; Manufacture: Panasonic - ECG; Manufacture Part Number: ERJ-1GEJ302C; Manufacture(English): Panasonic - ECG; Manufacture_Part_Number: ERJ-1GEJ302C; Manufacturer: Panasonic - ECG; Manufacturer_Part_No: ERJ-1GEJ302C; Mfg: Panasonic - ECG; Mfg Part#: ERJ-1GEJ302C; Mfr_name: Panasonic - ECG; Mfr_part_number: ERJ-1GEJ302C; Package: 0201; ProcessType: SMT; RoHS: Yes; Tolerance: 5%; Vendor: Digikey; Vendor Part#: P3.0KAGCT-ND; Vendor_Part_No: P3.0KAGCT-ND; eI Part#: 02_00960_01
R855 R859 = 10_R_0: RES 4.7K OHM 1/10W 5% 0402 SMD; Alt Mfg: Yageo; Alt Mfg Part#: RC0402JR-074K7L; Distributor_name: DIGIKEY; Distributor_part_number: P4.7KJCT-ND; EIC Part#: 02_00023_01; Manufacture: Panasonic - ECG; Manufacture Part Number: ERJ-2GEJ472X; Manufacture(English): Panasonic - ECG; Manufacture_Part_Number: ERJ-2GEJ472X; Manufacturer: Panasonic - ECG; Manufacturer_Part_No: ERJ-2GEJ472X; Mfg Part#: 02_00023_01; Mfr_name: Panasonic - ECG; Mfr_part_number: ERJ-2GEJ472X; Oper. Temp. Range: -55C to 125C; Package: 0402; ProcessType: SMT; Remark: Alt part is 1/16W; RoHS: Yes; Tolerance: 1%; Vendor: DIGIKEY; Vendor Part#: P4.7KJCT-ND; Vendor_Part_No: P4.7KJCT-ND; eI Part#: 02_00023_01
R860 = 10_R_0: RES 13.7K OHM 1/10W 1% 0402 SMD; Distributor_name: DIGIKEY; Distributor_part_number: P13.7KLCT-ND; EIC Part#: TBD; Manufacture: Panasonic - ECG; Manufacture Part Number: ERJ-2RKF1372X; Manufacture(English): Panasonic - ECG; Manufacture_Part_Number: ERJ-2RKF1372X; Manufacturer: Panasonic - ECG; Manufacturer_Part_No: ERJ-2RKF1372X; Mfg: Panasonic - ECG; Mfg Part#: ERJ-2RKF1372X; Mfr_name: Panasonic - ECG; Mfr_part_number: ERJ-2RKF1372X; Oper. Temp. Range: -55C ~ 125C; Package: 0402; ProcessType: SMT; Remark: Alt part is 1/10W; RoHS: Yes; Tolerance: 1%; Vendor: DigiKey; Vendor Part#: P13.7KLCT-ND; Vendor_Part_No: P13.7KLCT-ND; eI Part#: TBD
U28 U81 = TXS0102_0: IC VOLT-LEVEL TRANSLATOR US8; Alternate_Mfr: TI; Alternate_Partno: TXB0102DCUR; Distributor_name: DIGIKEY; Distributor_part_number: 296-21931-1-ND; EIC Part#: 01_00419_01; Manufacture: TI; Manufacture(English): TI; Manufacturer: TI; Mfg: TI; Mfg Part#: 01_00419_01; Mfr_name: TI; Price @ 1: 1.07000; Price @ 10K: 0.37125; Price @ 1K: 0.37868; Vendor: DIGIKEY; Vendor Part#: 296-21931-1-ND; Vendor_Part_No: 296-21931-1-ND; eI Part#: TBD
Y4 = CRYSTAL-4_PIN: CRYSTAL 25MHZ 18PF SMD; Distributor_name: DIGIKEY; Distributor_part_number: 535-9128-1-ND; EIC Part#: 08_00006_01; Manufacture: Abracon Corporation; Manufacture(English): Abracon Corporation; Manufacturer: Abracon Corporation; Mfg: Abracon Corporation; Mfg Part#: 08_00006_01; Mfr_name: Abracon Corporation; Oper. Temp. Range: -20C to 60C; Package: 5.0mm x 3.2mm; Price @ 1: 1.43000; Price @ 10K: 0.53200; Price @ 1K: 0.53200; RoHS: Yes; Specifications: CRYSTAL 25.000MHZ 18PF FUND SMD; Vendor: DIGIKEY; Vendor Part#: 535-9128-1-ND; Vendor_Part_No: 535-9128-1-ND; eI Part#: 08_00006_01

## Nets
AVCC3V3_1: PHY2.20(AVDD33_1) PHY2.25(AVDD33_2) PHY2.36(REG_IN) ; also on sheet 12
AVDD1V8_1: PHY2.3(AVDD18_1) PHY2.19(AVDD18_2) PHY2.26(AVDD18_3) PHY2.35(AVDDC18) PHY2.38(AVDD18_4) PHY2.39(AVDD18_OUT) ; also on sheet 12
DVDD1V0_1: PHY2.6(DVDD_1) PHY2.40(DVDD_OUT) PHY2.42(DVDD_2) ; also on sheet 12
GND: C185.2 C197.2 C205.2 C206.2 C209.2 C215.1 C236.1 C237.1 C649.2 C791.1 C795.2 C796.2 C804.1 C808.1 C812.1 C826.2 C827.2 C828.1 C829.1 C830.2 C831.2 C977.2 C978.2 PHY2.10(VDDO_SEL) PHY2.57(VSS) R292.2 R297.1 R299.1 R302.1 R306.1 R312.2 R313.1 R334.1 R620.1 R622.1 R651.1 R654.1 R656.1 R860.2 U28.2(GND) U81.2(GND) Y4.2 Y4.4 ; also on sheet 3 4 5 6 8 10 11 12 13 14 15 16 17 18 19 20 21 22 24 25 26 27 28 29 33 34 35 36 37 40 41 42 43 45 46 47
GND_LAN: CN4.10A(GND) CN4.SH1(P1_PTH_1) CN4.SH2(P1_PTH_2) ; also on sheet 12
VCC1V8: C185.1 FB6.1 R273.2 U28.3(VccA) ; also on sheet 6 8 11 19 21 22 25 26 27 29 33 34 36 37 41
VCC1V8_TCT: C197.1 FB6.2 R271.1 ; also on sheet 12
VCC2V5: C205.1 C977.1 CN4.11A(P1_COMMON1) CN4.13A(P1_COMMON2) PHY2.11(VDDO_1) PHY2.49(VDDO_2) PHY2.52(VDDO_3) R338.2 R855.2 R856.2 U28.7(VccB) U81.3(VccA) ; also on sheet 12
VCC3V3_AUX: C978.1 U81.7(VccB) ; also on sheet 4 6 8 11 12 13 16 18 19 22 25 26 27 28 29 33 35 37 40 45 47
VCCA0V75REF: C649.1 U30.F15(DDR3AVREFSSTL) ; also on sheet 19 20
VDD_DDR: C633.1 ; also on sheet 19 20 33 35 37
PCIe0/SGMII2_RXN_SOC: C218.1 ; also on sheet 40
PCIe0/SGMII2_RXN_SOC_NET: C218.2 U30.AJ22(CSISC2_3_RXN0)
PCIe0/SGMII2_RXP_SOC: C214.1 ; also on sheet 40
PCIe0/SGMII2_RXP_SOC_NET: C214.2 U30.AJ21(CSISC2_3_RXP0)
PCIe0/SGMII2_TXN_SOC: U30.AH20(CSISC2_3_TXN0) ; also on sheet 40
PCIe0/SGMII2_TXP_SOC: U30.AH21(CSISC2_3_TXP0) ; also on sheet 40
PCIe1/SGMII3_RXN_SOC: C241.1 ; also on sheet 40
PCIe1/SGMII3_RXN_SOC_NET: C241.2 U30.AK23(CSISC2_3_RXN1)
PCIe1/SGMII3_RXP_SOC: C235.1 ; also on sheet 40
PCIe1/SGMII3_RXP_SOC_NET: C235.2 U30.AK22(CSISC2_3_RXP1)
PCIe1/SGMII3_TXN_SOC: U30.AG21(CSISC2_3_TXN1) ; also on sheet 40
PCIe1/SGMII3_TXP_SOC: U30.AG22(CSISC2_3_TXP1) ; also on sheet 40
PHY1_LED_0: PHY2.14(LED[0]) R337.1
PHY1_LED_1: PHY2.13(LED[1]) R311.2 R609.1
PHY1_MDI0_N: CN4.1A(P1_TD1-) PHY2.27(MDI[0]_N)
PHY1_MDI0_P: CN4.2A(P1_TDP1+) PHY2.28(MDI[0]_P)
PHY1_MDI1_N: CN4.3A(P1_TD2-) PHY2.23(MDI[1]_N)
PHY1_MDI1_P: CN4.4A(P1_TD2+) PHY2.24(MDI[1]_P)
PHY1_MDI2_N: CN4.5A(P1_TD3-) PHY2.21(MDI[2]_N)
PHY1_MDI2_P: CN4.6A(P1_TD3+) PHY2.22(MDI[2]_P)
PHY1_MDI3_N: CN4.7A(P1_TD4-) PHY2.17(MDI[3]_N)
PHY1_MDI3_P: CN4.8A(P1_TD4+) PHY2.18(MDI[3]_P)
PHY_INT1#_FPGA_3V3_EXP4: U81.8(B1) ; also on sheet 27
PHY_INT1#_FPGA_3V3_EXP4_2V5: PHY2.12(LED[2]/INTn) R338.1 U81.5(A1)
PHY_INT2#_FPGA_3V3_EXP4: U81.1(B2) ; also on sheet 27
PHY_INT2#_FPGA_3V3_EXP4_2V5: U81.4(A2) ; also on sheet 12
PHY_RSTz: R859.1 ; also on sheet 5
PHY_RSTz_2V5: PHY2.16(RESETn) R859.2 R860.1 ; also on sheet 12
SGMII0_RXN_SOC: C256.1 PHY2.5(SOUT_N)
SGMII0_RXN_SOC_NET: C256.2 U30.AJ25(CSISC2_2_RXN0)
SGMII0_RXP_SOC: C247.1 PHY2.4(SOUT_P)
SGMII0_RXP_SOC_NET: C247.2 U30.AJ24(CSISC2_2_RXP0)
SGMII0_TXN_SOC: C286.1 U30.AH23(CSISC2_2_TXN0)
SGMII0_TXN_SOC_NET: C286.2 PHY2.2(SIN_N)
SGMII0_TXP_SOC: C285.1 U30.AH24(CSISC2_2_TXP0)
SGMII0_TXP_SOC_NET: C285.2 PHY2.1(SIN_P)
SGMII1_RXN_SOC: C262.1 ; also on sheet 12
SGMII1_RXN_SOC_NET: C262.2 U30.AK26(CSISC2_2_RXN1)
SGMII1_RXP_SOC: C259.1 ; also on sheet 12
SGMII1_RXP_SOC_NET: C259.2 U30.AK25(CSISC2_2_RXP1)
SGMII1_TXN_SOC: U30.AG24(CSISC2_2_TXN1) ; also on sheet 12
SGMII1_TXP_SOC: U30.AG25(CSISC2_2_TXP1) ; also on sheet 12
SOC_DDR3A_A0: R394.1 U30.C14(DDR3AA00) ; also on sheet 19 20
SOC_DDR3A_A1: R362.1 U30.D14(DDR3AA01) ; also on sheet 19 20
SOC_DDR3A_A2: R401.1 U30.A18(DDR3AA02) ; also on sheet 19 20
SOC_DDR3A_A3: R428.1 U30.E14(DDR3AA03) ; also on sheet 19 20
SOC_DDR3A_A4: R355.1 U30.C15(DDR3AA04) ; also on sheet 19 20
SOC_DDR3A_A5: R429.1 U30.A17(DDR3AA05) ; also on sheet 19 20
SOC_DDR3A_A6: R379.1 U30.D15(DDR3AA06) ; also on sheet 19 20
SOC_DDR3A_A7: R721.1 U30.B16(DDR3AA07) ; also on sheet 19 20
SOC_DDR3A_A8: R710.1 U30.B17(DDR3AA08) ; also on sheet 19 20
SOC_DDR3A_A9: R718.1 U30.D17(DDR3AA09) ; also on sheet 19 20
SOC_DDR3A_A10: R709.1 U30.B12(DDR3AA10) ; also on sheet 19 20
SOC_DDR3A_A11: R703.1 U30.B18(DDR3AA11) ; also on sheet 19 20
SOC_DDR3A_A12: R378.1 U30.C17(DDR3AA12) ; also on sheet 19 20
SOC_DDR3A_A13: R396.1 U30.B11(DDR3AA13) ; also on sheet 19 20
SOC_DDR3A_A14: R702.1 U30.E18(DDR3AA14) ; also on sheet 19 20
SOC_DDR3A_A15: R385.1 U30.E16(DDR3AA15) ; also on sheet 19 20
SOC_DDR3A_BA_0: R427.1 U30.E11(DDR3ABA0) ; also on sheet 19 20
SOC_DDR3A_BA_1: R363.1 U30.F12(DDR3ABA1) ; also on sheet 19 20
SOC_DDR3A_BA_2: R405.1 U30.E12(DDR3ABA2) ; also on sheet 19 20
SOC_DDR3A_CAS#: R745.1 U30.A13(DDR3ACASZ) ; also on sheet 19 20
SOC_DDR3A_CKE_0: R354.1 U30.E17(DDR3ACKE0) ; also on sheet 19 20
SOC_DDR3A_CKE_1: R692.1 U30.F17(DDR3ACKE1) ; also on sheet 19 20
SOC_DDR3A_CKN_0: R274.1 U30.A15(DDR3ACLKOUTN0) ; also on sheet 19 20
SOC_DDR3A_CKP_0: R284.1 U30.A16(DDR3ACLKOUTP0) ; also on sheet 19 20
SOC_DDR3A_CS_0#: R422.1 U30.A14(DDR3ACE0Z) ; also on sheet 19 20
SOC_DDR3A_CS_1#: R425.1 U30.A11(DDR3ACE1Z) ; also on sheet 19 20
SOC_DDR3A_DM_0: U30.E4(DDR3ADQM0) ; also on sheet 20
SOC_DDR3A_DM_1: U30.E5(DDR3ADQM1) ; also on sheet 20
SOC_DDR3A_DM_2: U30.A6(DDR3ADQM2) ; also on sheet 20
SOC_DDR3A_DM_3: U30.B8(DDR3ADQM3) ; also on sheet 20
SOC_DDR3A_DM_4: U30.F22(DDR3ADQM4) ; also on sheet 20
SOC_DDR3A_DM_5: U30.A23(DDR3ADQM5) ; also on sheet 20
SOC_DDR3A_DM_6: U30.C27(DDR3ADQM6) ; also on sheet 19
SOC_DDR3A_DM_7: U30.E28(DDR3ADQM7) ; also on sheet 19
SOC_DDR3A_DM_8: U30.A19(DDR3ADQM8) ; also on sheet 19
SOC_DDR3A_DQ0: U30.E1(DDR3AD00) ; also on sheet 20
SOC_DDR3A_DQ1: U30.C2(DDR3AD01) ; also on sheet 20
SOC_DDR3A_DQ2: U30.B2(DDR3AD02) ; also on sheet 20
SOC_DDR3A_DQ3: U30.C1(DDR3AD03) ; also on sheet 20
SOC_DDR3A_DQ4: U30.D1(DDR3AD04) ; also on sheet 20
SOC_DDR3A_DQ5: U30.D2(DDR3AD05) ; also on sheet 20
SOC_DDR3A_DQ6: U30.E2(DDR3AD06) ; also on sheet 20
SOC_DDR3A_DQ7: U30.E3(DDR3AD07) ; also on sheet 20
SOC_DDR3A_DQ8: U30.A5(DDR3AD08) ; also on sheet 20
SOC_DDR3A_DQ9: U30.D6(DDR3AD09) ; also on sheet 20
SOC_DDR3A_DQ10: U30.E6(DDR3AD10) ; also on sheet 20
SOC_DDR3A_DQ11: U30.B5(DDR3AD11) ; also on sheet 20
SOC_DDR3A_DQ12: U30.F6(DDR3AD12) ; also on sheet 20
SOC_DDR3A_DQ13: U30.D4(DDR3AD13) ; also on sheet 20
SOC_DDR3A_DQ14: U30.C4(DDR3AD14) ; also on sheet 20
SOC_DDR3A_DQ15: U30.F5(DDR3AD15) ; also on sheet 20
SOC_DDR3A_DQ16: U30.F8(DDR3AD16) ; also on sheet 20
SOC_DDR3A_DQ17: U30.E7(DDR3AD17) ; also on sheet 20
SOC_DDR3A_DQ18: U30.C6(DDR3AD18) ; also on sheet 20
SOC_DDR3A_DQ19: U30.B6(DDR3AD19) ; also on sheet 20
SOC_DDR3A_DQ20: U30.F7(DDR3AD20) ; also on sheet 20
SOC_DDR3A_DQ21: U30.E8(DDR3AD21) ; also on sheet 20
SOC_DDR3A_DQ22: U30.D8(DDR3AD22) ; also on sheet 20
SOC_DDR3A_DQ23: U30.C8(DDR3AD23) ; also on sheet 20
SOC_DDR3A_DQ24: U30.F10(DDR3AD24) ; also on sheet 20
SOC_DDR3A_DQ25: U30.D10(DDR3AD25) ; also on sheet 20
SOC_DDR3A_DQ26: U30.E10(DDR3AD26) ; also on sheet 20
SOC_DDR3A_DQ27: U30.C10(DDR3AD27) ; also on sheet 20
SOC_DDR3A_DQ28: U30.A9(DDR3AD28) ; also on sheet 20
SOC_DDR3A_DQ29: U30.A8(DDR3AD29) ; also on sheet 20
SOC_DDR3A_DQ30: U30.B9(DDR3AD30) ; also on sheet 20
SOC_DDR3A_DQ31: U30.E9(DDR3AD31) ; also on sheet 20
SOC_DDR3A_DQ32: U30.A21(DDR3AD32) ; also on sheet 20
SOC_DDR3A_DQ33: U30.B21(DDR3AD33) ; also on sheet 20
SOC_DDR3A_DQ34: U30.C21(DDR3AD34) ; also on sheet 20
SOC_DDR3A_DQ35: U30.D21(DDR3AD35) ; also on sheet 20
SOC_DDR3A_DQ36: U30.E22(DDR3AD36) ; also on sheet 20
SOC_DDR3A_DQ37: U30.E21(DDR3AD37) ; also on sheet 20
SOC_DDR3A_DQ38: U30.E23(DDR3AD38) ; also on sheet 20
SOC_DDR3A_DQ39: U30.F23(DDR3AD39) ; also on sheet 20
SOC_DDR3A_DQ40: U30.F25(DDR3AD40) ; also on sheet 20
SOC_DDR3A_DQ41: U30.D25(DDR3AD41) ; also on sheet 20
SOC_DDR3A_DQ42: U30.C23(DDR3AD42) ; also on sheet 20
SOC_DDR3A_DQ43: U30.E25(DDR3AD43) ; also on sheet 20
SOC_DDR3A_DQ44: U30.E24(DDR3AD44) ; also on sheet 20
SOC_DDR3A_DQ45: U30.D23(DDR3AD45) ; also on sheet 20
SOC_DDR3A_DQ46: U30.F24(DDR3AD46) ; also on sheet 20
SOC_DDR3A_DQ47: U30.B23(DDR3AD47) ; also on sheet 20
SOC_DDR3A_DQ48: U30.C25(DDR3AD48) ; also on sheet 19
SOC_DDR3A_DQ49: U30.B25(DDR3AD49) ; also on sheet 19
SOC_DDR3A_DQ50: U30.A25(DDR3AD50) ; also on sheet 19
SOC_DDR3A_DQ51: U30.A27(DDR3AD51) ; also on sheet 19
SOC_DDR3A_DQ52: U30.E26(DDR3AD52) ; also on sheet 19
SOC_DDR3A_DQ53: U30.E27(DDR3AD53) ; also on sheet 19
SOC_DDR3A_DQ54: U30.D27(DDR3AD54) ; also on sheet 19
SOC_DDR3A_DQ55: U30.B27(DDR3AD55) ; also on sheet 19
SOC_DDR3A_DQ56: U30.E30(DDR3AD56) ; also on sheet 19
SOC_DDR3A_DQ57: U30.E29(DDR3AD57) ; also on sheet 19
SOC_DDR3A_DQ58: U30.F29(DDR3AD58) ; also on sheet 19
SOC_DDR3A_DQ59: U30.D30(DDR3AD59) ; also on sheet 19
SOC_DDR3A_DQ60: U30.C30(DDR3AD60) ; also on sheet 19
SOC_DDR3A_DQ61: U30.D29(DDR3AD61) ; also on sheet 19
SOC_DDR3A_DQ62: U30.B28(DDR3AD62) ; also on sheet 19
SOC_DDR3A_DQ63: U30.A28(DDR3AD63) ; also on sheet 19
SOC_DDR3A_DQSN_0: U30.B3(DDR3ADQS0N) ; also on sheet 20
SOC_DDR3A_DQSN_1: U30.A4(DDR3ADQS1N) ; also on sheet 20
SOC_DDR3A_DQSN_2: U30.B7(DDR3ADQS2N) ; also on sheet 20
SOC_DDR3A_DQSN_3: U30.B10(DDR3ADQS3N) ; also on sheet 20
SOC_DDR3A_DQSN_4: U30.B22(DDR3ADQS4N) ; also on sheet 20
SOC_DDR3A_DQSN_5: U30.A24(DDR3ADQS5N) ; also on sheet 20
SOC_DDR3A_DQSN_6: U30.A26(DDR3ADQS6N) ; also on sheet 19
SOC_DDR3A_DQSN_7: U30.B29(DDR3ADQS7N) ; also on sheet 19
SOC_DDR3A_DQSN_8: U30.B20(DDR3ADQS8N) ; also on sheet 19
SOC_DDR3A_DQSP_0: U30.A3(DDR3ADQS0P) ; also on sheet 20
SOC_DDR3A_DQSP_1: U30.B4(DDR3ADQS1P) ; also on sheet 20
SOC_DDR3A_DQSP_2: U30.A7(DDR3ADQS2P) ; also on sheet 20
SOC_DDR3A_DQSP_3: U30.A10(DDR3ADQS3P) ; also on sheet 20
SOC_DDR3A_DQSP_4: U30.A22(DDR3ADQS4P) ; also on sheet 20
SOC_DDR3A_DQSP_5: U30.B24(DDR3ADQS5P) ; also on sheet 20
SOC_DDR3A_DQSP_6: U30.B26(DDR3ADQS6P) ; also on sheet 19
SOC_DDR3A_DQSP_7: U30.C29(DDR3ADQS7P) ; also on sheet 19
SOC_DDR3A_DQSP_8: U30.A20(DDR3ADQS8P) ; also on sheet 19
SOC_DDR3A_ECC0: U30.F19(DDR3ACB00) ; also on sheet 19
SOC_DDR3A_ECC1: U30.F20(DDR3ACB01) ; also on sheet 19
SOC_DDR3A_ECC2: U30.F18(DDR3ACB02) ; also on sheet 19
SOC_DDR3A_ECC3: U30.E20(DDR3ACB03) ; also on sheet 19
SOC_DDR3A_ECC4: U30.E19(DDR3ACB04) ; also on sheet 19
SOC_DDR3A_ECC5: U30.D19(DDR3ACB05) ; also on sheet 19
SOC_DDR3A_ECC6: U30.C19(DDR3ACB06) ; also on sheet 19
SOC_DDR3A_ECC7: U30.B19(DDR3ACB07) ; also on sheet 19
SOC_DDR3A_ODT_0: R424.1 U30.A12(DDR3AODT0) ; also on sheet 19 20
SOC_DDR3A_ODT_1: R744.1 U30.F11(DDR3AODT1) ; also on sheet 19 20
SOC_DDR3A_RAS#: R423.1 U30.B13(DDR3ARASZ) ; also on sheet 19 20
SOC_DDR3A_RESETN: U30.E15(DDR3ARESETZ) ; also on sheet 19 20
SOC_DDR3A_WE#: R426.1 U30.D12(DDR3AWEZ) ; also on sheet 19 20
SOC_MDC: U28.5(A1) U30.G2(MDCLK)
SOC_MDC_2V5: PHY2.7(MDC) U28.8(B1) ; also on sheet 12 18
SOC_MDIO: U28.4(A2) U30.H1(MDIO)
SOC_MDIO_2V5: PHY2.8(MDIO) R855.1 U28.1(B2) ; also on sheet 12 18
VTT_DDR3A: C791.2 C795.1 C796.1 C804.2 C808.2 C812.2 C826.1 C827.1 C828.2 C829.2 C830.1 C831.1 R354.2 R355.2 R362.2 R363.2 R378.2 R379.2 R385.2 R394.2 R396.2 R401.2 R405.2 R422.2 R423.2 R424.2 R425.2 R426.2 R427.2 R428.2 R429.2 R692.2 R702.2 R703.2 R709.2 R710.2 R718.2 R721.2 R744.2 R745.2 ; also on sheet 19 37
N17701525: C633.2 R274.2 R284.2
N18077727: PHY2.9(CLK125) TP68.1
N18077740: C237.2 PHY2.33(XTAL_OUT) Y4.3
N18077748: C236.2 PHY2.34(XTAL_IN) Y4.1
N18077862: PHY2.30(RSET) R292.1
N18077881: PHY2.29(TSTPT) TP67.1
N18077890: PHY2.31(HSDAC_N) TP66.1
N18077892: PHY2.32(HSDAC_P) TP65.1
N18077906: C230.1 PHY2.41(REGCAP2)
N18077912: C230.2 PHY2.37(REGCAP1)
N18077984: PHY2.53(TX_CLK) R302.2
N18077986: PHY2.56(TX_CTRL) R334.2
N18077988: PHY2.55(TXD[3]) R313.2
N18077990: PHY2.54(TXD[2]) R306.2
N18077992: PHY2.51(TXD[1]) R299.2
N18077996: PHY2.50(TXD[0]) R297.2
N18077998: PHY2.15(CONFIG) R311.1 R312.1
N18081024: CN4.12A(P1_GREEN) R337.2
N18081026: CN4.14A(P1_ORANGE) R609.2
N18148600: R273.1 U28.6(OE)
N18396620: TP61.1 U30.C12(DDR3AATO)
N18400161: R622.2 U30.F13(DDR3ARZQ0)
N18400191: R620.2 U30.F9(DDR3ARZQ1)
N18400194: R656.2 U30.F21(DDR3ARZQ2)
N18400428: TP60.1 U30.E13(DDR3ADTO0)
N18400431: TP62.1 U30.F14(DDR3ADTO1)
N20995958: C206.1 C209.1 C215.2 CN4.9A(P1_VCC) R271.2
N20998497: R270.1 U30.B14(DDR3ACLKOUTN1)
N20998500: R270.2 U30.B15(DDR3ACLKOUTP1)
N21870840: R654.2 U30.AE23(CSISC2_2_REFRES)
N21870948: R651.2 U30.AE22(CSISC2_3_REFRES)
N22867306: R856.1 U81.6(OE)

Not connected (* = marked no-connect by the designer): CN4 MH1(NPTH_1)* MH2(NPTH_2)*; PHY2 43(RX_CTRL)* 44(RXD[0])* 45(RXD[1])* 46(RX_CLK)* 47(RXD[2])* 48(RXD[3])*; U30 AE21(CSISC2_3_TEST) AF22(CSISC2_2_TEST)

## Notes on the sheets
sheet 1
- K2L DDR3
- Place these resistors at the
  end of the trace.
- Place these resistors at the
  end of the trace.
sheet 2
- Ethernet PHY, Magnetics for 2 channel/ Tx/Rx,
  MDC/MDIO for AMC, K2L SGMII/ PCIe
- ETHERNET PHY 1
- Magnetics for 2 channel/ Tx/Rx
- MDC/MDIO for AMC
- CONFIG
  Bit1
- CONFIG
  Bit0
- Value
  Assignment
- Pin
- PHY ADDRESS :- 0x0
- PHYAD[0]=0
- Config
- 0
- 0
- VDDO_LEVEL=3.3V
- Config
- 1
- 1
- PHYAD[0]=1
- K2L SGMII/ PCIe
- VDDO_LEVEL=3.3V
- Config
- 0
- PHYAD[0]=0
- 1
- VDDO_LEVEL=2.5V
- PHYAD[0]=1
- Config
- 0
- 1
- VDDO_LEVEL=2.5V
